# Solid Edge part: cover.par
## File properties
Author: Robert a Rhodes jr
Template: NORMENG.PAR
Last saved by: TIET
Revision: 9
Application: Solid Edge
Accuracy: 0.99
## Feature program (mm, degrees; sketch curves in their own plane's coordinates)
sketch for "unnamed Protrusion 1" plane through (0, 0, 0) normal (0, 0, 1) x-axis (1, 0, 0)
  line (0, 0) -> (0, 0)
  circle centre (0, 0) radius 88.9
extrude "unnamed Protrusion 1" add finite 63.5 along -normal
fillet "Round_1" radius 25.4
thinwall "Thinwall_1"  Thickness = 6.35 mm
sketch for "ExtrudedProtrusion_3" #1 plane through (-1.5818, 0.3164, -63.5) normal (0, 0, -1) x-axis (-1, 0, 0)
  circle centre (-1.5818, 107.6336) radius 9.525
sketch for "ExtrudedProtrusion_3" #2 plane through (-1.5818, 0.3164, -63.5) normal (0, 0, -1) x-axis (-1, 0, 0)
  line (-20.6318, 86.5186) -> (-20.6318, 107.6336)
  arc centre (-1.5818, 107.6336) radius 19.05 from (-20.6318, 107.6336) to (17.4682, 107.6336) cw
  line (17.4682, 107.6336) -> (17.4682, 86.5186)
  arc centre (-1.5818, -0.3164) radius 88.9 from (17.4682, 86.5186) to (-20.6318, 86.5186) ccw
extrude "ExtrudedProtrusion_3" add finite 12.7 along -normal
pattern "unnamed Pattern 1" of "ExtrudedProtrusion_3"
extrude "unnamed Protrusion 2" add finite 12.7
extrude "unnamed Protrusion 3" add finite 12.7
sketch for "ExtrudedProtrusion_6" plane through (0, 0, 0) normal (0, 0, 1) x-axis (1, 0, 0)
  circle centre (0, 0) radius 31.75
extrude "ExtrudedProtrusion_6" add finite 19.05 along +normal
fillet "Round_2" radius 5.08
sketch used by "unnamed Cutout 1" plane through (0, 0, 0) normal (0, 0, 1) x-axis (1, 0, 0)
extrude "unnamed Cutout 1" cut through along -normal
pattern "unnamed Pattern 2" of "unnamed Cutout 1"
extrude "unnamed Cutout 2" cut through
extrude "unnamed Cutout 3" cut through
extrude "unnamed Cutout 4" cut through
extrude "unnamed Cutout 5" cut through
extrude "unnamed Cutout 6" cut through
extrude "unnamed Cutout 7" cut through
sketch for "unnamed Protrusion 4" plane through (0, 0, 0) normal (0, 0, -1) x-axis (0, -1, 0)
  circle centre (0, 0) radius 31.75
extrude "unnamed Protrusion 4" add along +normal
sketch for "Hole_1" plane through (0, 0, 19.05) normal (0, 0, 1) x-axis (1, 0, 0)
  hole centre (0, 0) bore radius 19.05
hole "Hole_1" diameter 38.1 through
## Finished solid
Body 1: solid body, 66 faces, 205 edges, 128 vertices.
  Faces by surface: plane 39, cylinder 24, torus 3
  Edges by curve: line 112, circle 69, intersection 24
Bounding box of the edges (mm; curved faces can reach further): 225.075 x 215.900 x 82.550, from (-112.5374, -88.9, -63.5) to (112.5374, 127, 19.05).
Cylindrical faces by radius (mm): R3.81 x14, R9.525 x3, R19.05 x4, R31.75 x1, R82.55 x1, R88.9 x1
Toroidal faces (ring radius, tube radius in mm): R26.67 r5.08 x1, R63.5 r19.05 x1, R63.5 r25.4 x1
Planar faces by outward normal: +x 12, +z 7, -x 12, -z 4, oblique 4
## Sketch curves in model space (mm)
arc centre (-45.72, -50.8, 0) radius 3.81 from (-41.91, -50.8, 0) through (-45.8329, -54.6083, 0) to (-49.53, -50.8, 0)
line (-49.53, -50.8, 0) -> (-49.53, 50.8, 0)
arc centre (-45.72, 50.8, 0) radius 3.81 from (-49.53, 50.8, 0) through (-45.6071, 54.6083, 0) to (-41.91, 50.8, 0)
line (-41.91, 50.8, 0) -> (-41.91, -50.8, 0)
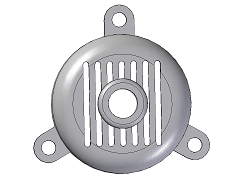
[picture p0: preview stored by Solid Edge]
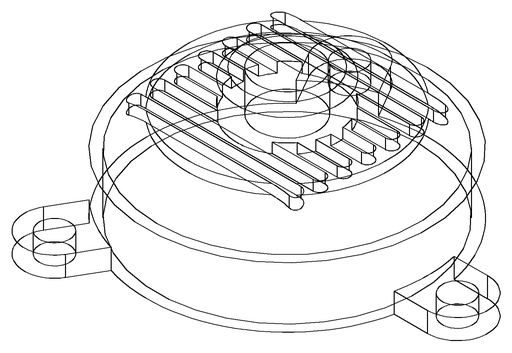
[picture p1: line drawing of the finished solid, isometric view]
